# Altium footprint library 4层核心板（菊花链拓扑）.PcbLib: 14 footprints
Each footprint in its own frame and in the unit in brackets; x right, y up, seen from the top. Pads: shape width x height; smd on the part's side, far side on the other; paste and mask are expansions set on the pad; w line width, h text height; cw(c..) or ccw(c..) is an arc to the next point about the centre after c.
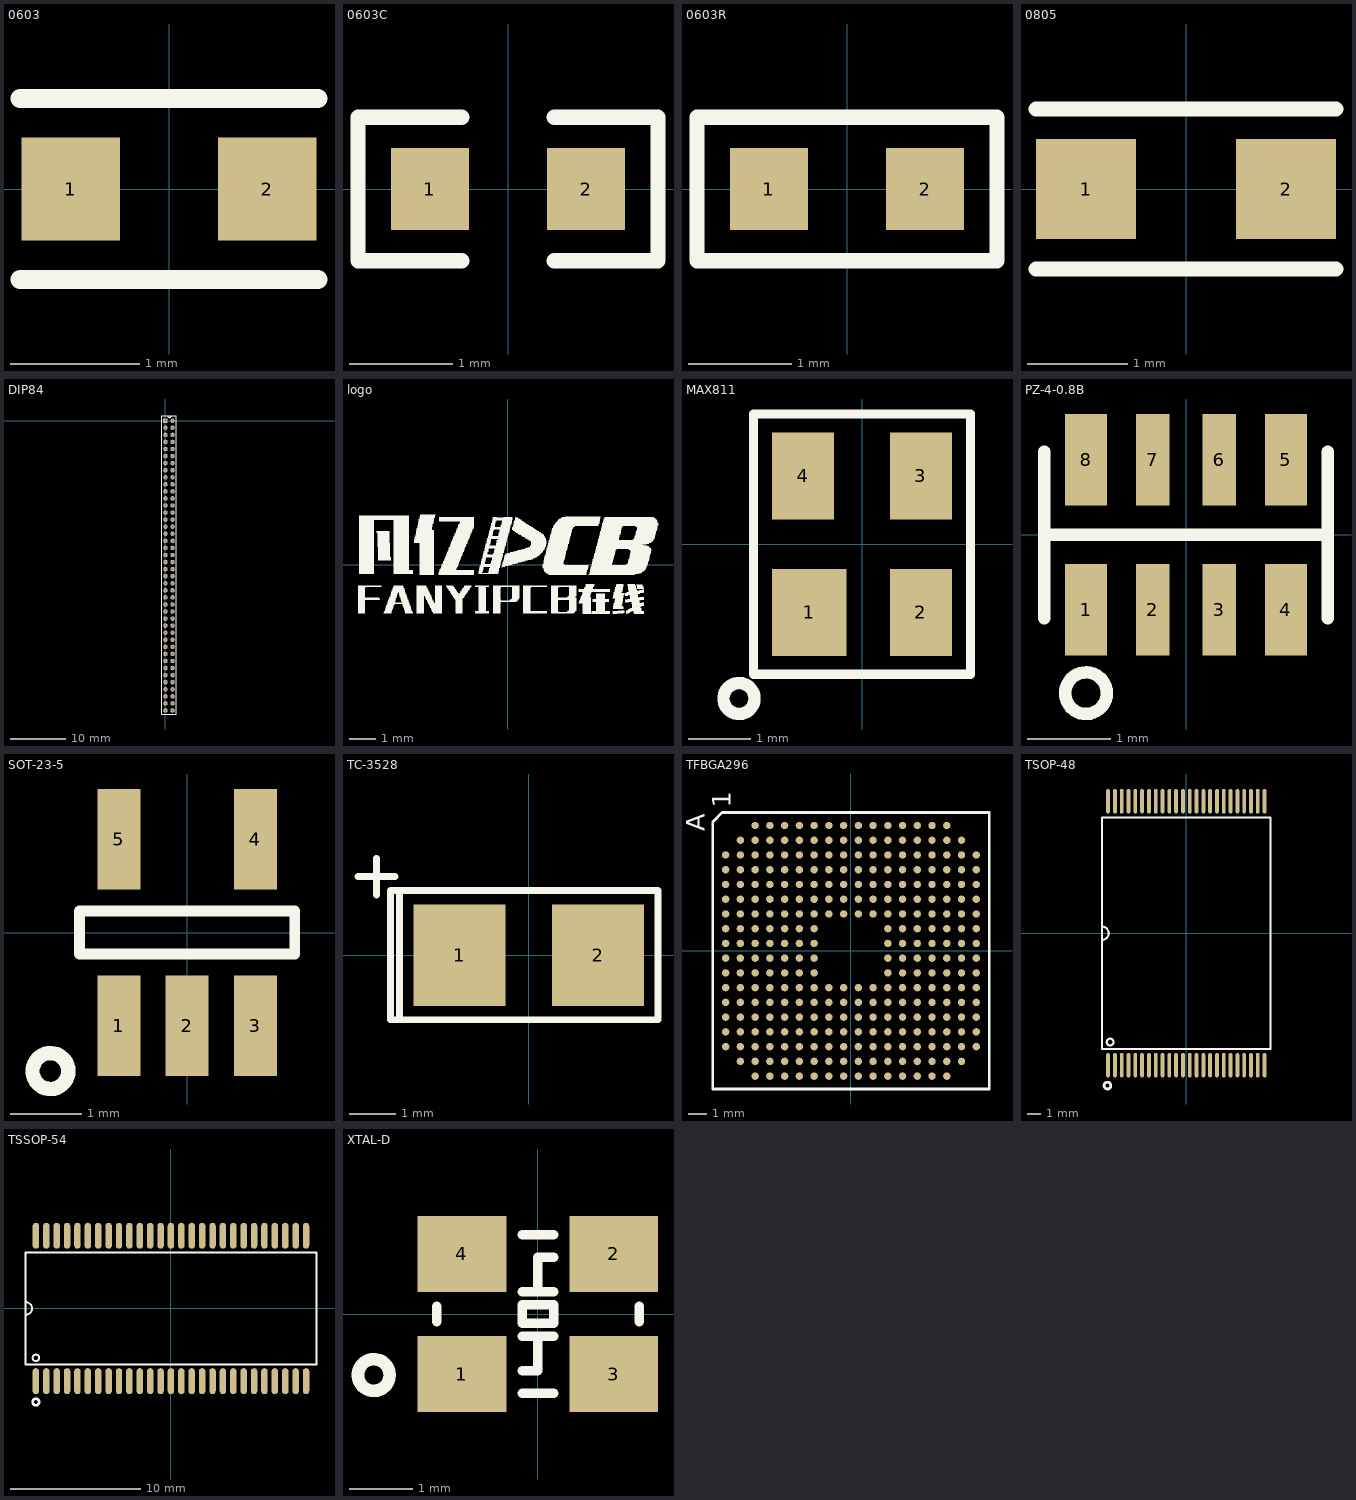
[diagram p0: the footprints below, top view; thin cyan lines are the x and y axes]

## 0603 [mm]
pads (2):
  rect 0.76x0.8 smd: 1(-0.76,0) 2(0.76,0)
Top Overlay:
  lines w0.15: -1.15,-0.7 1.15,-0.7 ; -1.15,0.7 1.15,0.7

## 0603C [mm]
pads (2):
  rect 0.76x0.8 smd: 1(-0.76,0) 2(0.76,0)
Top Overlay:
  lines w0.15: -0.45,-0.7 -1.46,-0.7 -1.46,0.7 -0.45,0.7 ; 0.45,-0.7 1.46,-0.7 1.46,0.7 0.45,0.7

## 0603R [mm]
pads (2):
  rect 0.76x0.8 smd: 1(-0.76,0) 2(0.76,0)
Top Overlay:
  lines w0.15: -1.46,-0.7 -1.46,0.7 1.46,0.7 1.46,-0.7 -1.46,-0.7

## 0805 [mm]
pads (2):
  rect 1x1 smd: 1(-1,0) 2(1,0)
Top Overlay:
  lines w0.15: -1.5,-0.8 1.5,-0.8 ; -1.5,0.8 1.5,0.8

## DIP84 [mm]
pads (84):
  rect 0.8x0.8 hole 0.55: 1(0,0)
  round 0.8 hole 0.55: 2(1.27,0) 3(0,-1.27) 4(1.27,-1.27) 5(0,-2.54) 6(1.27,-2.54) 7(0,-3.81) 8(1.27,-3.81) 9(0,-5.08) 10(1.27,-5.08) 11(0,-6.35) 12(1.27,-6.35) 13(0,-7.62) 14(1.27,-7.62) 15(0,-8.89) 16(1.27,-8.89) 17(0,-10.16) 18(1.27,-10.16) 19(0,-11.43) 20(1.27,-11.43) 21(0,-12.7) 22(1.27,-12.7) 23(0,-13.97) 24(1.27,-13.97) 25(0,-15.24) 26(1.27,-15.24) 27(0,-16.51) 28(1.27,-16.51) 29(0,-17.78) 30(1.27,-17.78) 31(0,-19.05) 32(1.27,-19.05) 33(0,-20.32) 34(1.27,-20.32) 35(0,-21.59) 36(1.27,-21.59) 37(0,-22.86) 38(1.27,-22.86) 39(0,-24.13) 40(1.27,-24.13) 41(0,-25.4) 42(1.27,-25.4) 43(0,-26.67) 44(1.27,-26.67) 45(0,-27.94) 46(1.27,-27.94) 47(0,-29.21) 48(1.27,-29.21) 49(0,-30.48) 50(1.27,-30.48) 51(0,-31.75) 52(1.27,-31.75) 53(0,-33.02) 54(1.27,-33.02) 55(0,-34.29) 56(1.27,-34.29) 57(0,-35.56) 58(1.27,-35.56) 59(0,-36.83) 60(1.27,-36.83) 61(0,-38.1) 62(1.27,-38.1) 63(0,-39.37) 64(1.27,-39.37) 65(0,-40.64) 66(1.27,-40.64) 67(0,-41.91) 68(1.27,-41.91) 69(0,-43.18) 70(1.27,-43.18) 71(0,-44.45) 72(1.27,-44.45) 73(0,-45.72) 74(1.27,-45.72) 75(0,-46.99) 76(1.27,-46.99) 77(0,-48.26) 78(1.27,-48.26) 79(0,-49.53) 80(1.27,-49.53) 81(0,-50.8) 82(1.27,-50.8) 83(0,-52.07) 84(1.27,-52.07)
Top Overlay:
  lines w0.15: 0.381,0.889 ccw(c0.699,0.889) 1.016,0.889 ; -0.635,-52.705 1.905,-52.705 1.905,0.889 -0.635,0.889 -0.635,-52.705

## logo [mm]
Top Overlay:
  drawing of 1471 lines, arcs and shapes, not listed

## MAX811 [mm]
pads (4):
  rect 1.2x1.4 smd: 1(-0.85,-1.1)
  rect 1x1.4 smd: 2(0.95,-1.1) 3(0.95,1.1) 4(-0.95,1.1)
Top Overlay:
  circle w0.2: c-1.985,-2.489 r0.25
  lines w0.15: -1.6,2.1 1.75,2.1 1.75,-2.1 -1.75,-2.1 -1.75,2.1 -1.5,2.1

## PZ-4-0.8B [mm]
pads (8):
  rect 0.5x1.1 smd: 1(-1.2,-0.9) 4(1.2,-0.9) 5(1.2,0.9) 8(-1.2,0.9)
  rect 0.4x1.1 smd: 2(-0.4,-0.9) 3(0.4,-0.9) 6(0.4,0.9) 7(-0.4,0.9)
Top Overlay:
  circle w0.15: c-1.2,-1.9 r0.25
  lines w0.15: -1.7,-1 -1.7,1 ; -1.7,0 1.7,0 ; 1.7,-1 1.7,1

## SOT-23-5 [mm]
pads (5):
  rect 0.6x1.4 smd: 1(-0.95,-1.3) 2(0,-1.3) 3(0.95,-1.3) 4(0.95,1.3) 5(-0.95,1.3)
Top Overlay:
  circle w0.2: c-1.905,-1.931 r0.25
  lines w0.15: -1.5,-0.3 -1.5,0.3 1.5,0.3 1.5,-0.3 -1.5,-0.3

## TC-3528 [mm]
pads (2):
  rect 2x2.2 smd: 1(-1.5,0) 2(1.5,0)
Top Overlay:
  lines w0.15: -3.7,1.7 -2.9,1.7 ; -3.3,1.3 -3.3,2.1 ; -2.8,-1.4 -3,-1.4 -3,1.4 -2.8,1.4 ; -2.8,-1.4 -2.8,1.4 ; -2.8,-1.4 2.8,-1.4 2.8,1.4 -2.8,1.4

## TFBGA296 [mm]
pads (296):
  round 0.4 smd: A3(-5.2,6.8) A4(-4.4,6.8) A5(-3.6,6.8) A6(-2.8,6.8) A7(-2,6.8) A8(-1.2,6.8) A9(-0.4,6.8) A10(0.4,6.8) A11(1.2,6.8) A12(2,6.8) A13(2.8,6.8) A14(3.6,6.8) A15(4.4,6.8) A16(5.2,6.8) B2(-6,6) B3(-5.2,6) B4(-4.4,6) B5(-3.6,6) B6(-2.8,6) B7(-2,6) B8(-1.2,6) B9(-0.4,6) B10(0.4,6) B11(1.2,6) B12(2,6) B13(2.8,6) B14(3.6,6) B15(4.4,6) B16(5.2,6) B17(6,6) C1(-6.8,5.2) C2(-6,5.2) C3(-5.2,5.2) C4(-4.4,5.2) C5(-3.6,5.2) C6(-2.8,5.2) C7(-2,5.2) C8(-1.2,5.2) C9(-0.4,5.2) C10(0.4,5.2) C11(1.2,5.2) C12(2,5.2) C13(2.8,5.2) C14(3.6,5.2) C15(4.4,5.2) C16(5.2,5.2) C17(6,5.2) C18(6.8,5.2) D1(-6.8,4.4) D2(-6,4.4) D3(-5.2,4.4) D4(-4.4,4.4) D5(-3.6,4.4) D6(-2.8,4.4) D7(-2,4.4) D8(-1.2,4.4) D9(-0.4,4.4) D10(0.4,4.4) D11(1.2,4.4) D12(2,4.4) D13(2.8,4.4) D14(3.6,4.4) D15(4.4,4.4) D16(5.2,4.4) D17(6,4.4) D18(6.8,4.4) E1(-6.8,3.6) E2(-6,3.6) E3(-5.2,3.6) E4(-4.4,3.6) E5(-3.6,3.6) E6(-2.8,3.6) E7(-2,3.6) E8(-1.2,3.6) E9(-0.4,3.6) E10(0.4,3.6) E11(1.2,3.6) E12(2,3.6) E13(2.8,3.6) E14(3.6,3.6) E15(4.4,3.6) E16(5.2,3.6) E17(6,3.6) E18(6.8,3.6) F1(-6.8,2.8) F2(-6,2.8) F3(-5.2,2.8) F4(-4.4,2.8) F5(-3.6,2.8) F6(-2.8,2.8) F7(-2,2.8) F8(-1.2,2.8) F9(-0.4,2.8) F10(0.4,2.8) F11(1.2,2.8) F12(2,2.8) F13(2.8,2.8) F14(3.6,2.8) F15(4.4,2.8) F16(5.2,2.8) F17(6,2.8) F18(6.8,2.8) G1(-6.8,2) G2(-6,2) G3(-5.2,2) G4(-4.4,2) G5(-3.6,2) G6(-2.8,2) G7(-2,2) G8(-1.2,2) G9(-0.4,2) G10(0.4,2) G11(1.2,2) G12(2,2) G13(2.8,2) G14(3.6,2) G15(4.4,2) G16(5.2,2) G17(6,2) G18(6.8,2) H1(-6.8,1.2) H2(-6,1.2) H3(-5.2,1.2) H4(-4.4,1.2) H5(-3.6,1.2) H6(-2.8,1.2) H7(-2,1.2) H12(2,1.2) H13(2.8,1.2) H14(3.6,1.2) H15(4.4,1.2) H16(5.2,1.2) H17(6,1.2) H18(6.8,1.2) J1(-6.8,0.4) J2(-6,0.4) J3(-5.2,0.4) J4(-4.4,0.4) J5(-3.6,0.4) J6(-2.8,0.4) J7(-2,0.4) J12(2,0.4) J13(2.8,0.4) J14(3.6,0.4) J15(4.4,0.4) J16(5.2,0.4) J17(6,0.4) J18(6.8,0.4) K1(-6.8,-0.4) K2(-6,-0.4) K3(-5.2,-0.4) K4(-4.4,-0.4) K5(-3.6,-0.4) K6(-2.8,-0.4) K7(-2,-0.4) K12(2,-0.4) K13(2.8,-0.4) K14(3.6,-0.4) K15(4.4,-0.4) K16(5.2,-0.4) K17(6,-0.4) K18(6.8,-0.4) L1(-6.8,-1.2) L2(-6,-1.2) L3(-5.2,-1.2) L4(-4.4,-1.2) L5(-3.6,-1.2) L6(-2.8,-1.2) L7(-2,-1.2) L12(2,-1.2) L13(2.8,-1.2) L14(3.6,-1.2) L15(4.4,-1.2) L16(5.2,-1.2) L17(6,-1.2) L18(6.8,-1.2) M1(-6.8,-2) M2(-6,-2) M3(-5.2,-2) M4(-4.4,-2) M5(-3.6,-2) M6(-2.8,-2) M7(-2,-2) M8(-1.2,-2) M9(-0.4,-2) M10(0.4,-2) M11(1.2,-2) M12(2,-2) M13(2.8,-2) M14(3.6,-2) M15(4.4,-2) M16(5.2,-2) M17(6,-2) M18(6.8,-2) N1(-6.8,-2.8) N2(-6,-2.8) N3(-5.2,-2.8) N4(-4.4,-2.8) N5(-3.6,-2.8) N6(-2.8,-2.8) N7(-2,-2.8) N8(-1.2,-2.8) N9(-0.4,-2.8) N10(0.4,-2.8) N11(1.2,-2.8) N12(2,-2.8) N13(2.8,-2.8) N14(3.6,-2.8) N15(4.4,-2.8) N16(5.2,-2.8) N17(6,-2.8) N18(6.8,-2.8) P1(-6.8,-3.6) P2(-6,-3.6) P3(-5.2,-3.6) P4(-4.4,-3.6) P5(-3.6,-3.6) P6(-2.8,-3.6) P7(-2,-3.6) P8(-1.2,-3.6) P9(-0.4,-3.6) P10(0.4,-3.6) P11(1.2,-3.6) P12(2,-3.6) P13(2.8,-3.6) P14(3.6,-3.6) P15(4.4,-3.6) P16(5.2,-3.6) P17(6,-3.6) P18(6.8,-3.6) R1(-6.8,-4.4) R2(-6,-4.4) R3(-5.2,-4.4) R4(-4.4,-4.4) R5(-3.6,-4.4) R6(-2.8,-4.4) R7(-2,-4.4) R8(-1.2,-4.4) R9(-0.4,-4.4) R10(0.4,-4.4) R11(1.2,-4.4) R12(2,-4.4) R13(2.8,-4.4) R14(3.6,-4.4) R15(4.4,-4.4) R16(5.2,-4.4) R17(6,-4.4) R18(6.8,-4.4) T1(-6.8,-5.2) T2(-6,-5.2) T3(-5.2,-5.2) T4(-4.4,-5.2) T5(-3.6,-5.2) T6(-2.8,-5.2) T7(-2,-5.2) T8(-1.2,-5.2) T9(-0.4,-5.2) T10(0.4,-5.2) T11(1.2,-5.2) T12(2,-5.2) T13(2.8,-5.2) T14(3.6,-5.2) T15(4.4,-5.2) T16(5.2,-5.2) T17(6,-5.2) T18(6.8,-5.2) U2(-6,-6) U3(-5.2,-6) U4(-4.4,-6) U5(-3.6,-6) U6(-2.8,-6) U7(-2,-6) U8(-1.2,-6) U9(-0.4,-6) U10(0.4,-6) U11(1.2,-6) U12(2,-6) U13(2.8,-6) U14(3.6,-6) U15(4.4,-6) U16(5.2,-6) U17(6,-6) V3(-5.2,-6.8) V4(-4.4,-6.8) V5(-3.6,-6.8) V6(-2.8,-6.8) V7(-2,-6.8) V8(-1.2,-6.8) V9(-0.4,-6.8) V10(0.4,-6.8) V11(1.2,-6.8) V12(2,-6.8) V13(2.8,-6.8) V14(3.6,-6.8) V15(4.4,-6.8) V16(5.2,-6.8)
Top Overlay:
  lines w0.15: -7.5,-7.5 -7.5,7 -7,7.5 7.5,7.5 7.5,-7.5 -7.5,-7.5
  text "1" at -6.534,7.764 h1.02
  text "A" at -7.931,6.494 h1.02

## TSOP-48 [mm]
pads (48):
  oval 0.28x1.8 smd: 1(-5.75,-9.7) 2(-5.25,-9.7) 3(-4.75,-9.7) 4(-4.25,-9.7) 5(-3.75,-9.7) 6(-3.25,-9.7) 7(-2.75,-9.7) 8(-2.25,-9.7) 9(-1.75,-9.7) 10(-1.25,-9.7) 11(-0.75,-9.7) 12(-0.25,-9.7) 13(0.25,-9.7) 14(0.75,-9.7) 15(1.25,-9.7) 16(1.75,-9.7) 17(2.25,-9.7) 18(2.75,-9.7) 19(3.25,-9.7) 20(3.75,-9.7) 21(4.25,-9.7) 22(4.75,-9.7) 23(5.25,-9.7) 24(5.75,-9.7) 25(5.75,9.7) 26(5.25,9.7) 27(4.75,9.7) 28(4.25,9.7) 29(3.75,9.7) 30(3.25,9.7) 31(2.75,9.7) 32(2.25,9.7) 33(1.75,9.7) 34(1.25,9.7) 35(0.75,9.7) 36(0.25,9.7) 37(-0.25,9.7) 38(-0.75,9.7) 39(-1.25,9.7) 40(-1.75,9.7) 41(-2.25,9.7) 42(-2.75,9.7) 43(-3.25,9.7) 44(-3.75,9.7) 45(-4.25,9.7) 46(-4.75,9.7) 47(-5.25,9.7) 48(-5.75,9.7)
Top Overlay:
  circle w0.15: c-5.6,-8 r0.25
  circle w0.2: c-5.8,-11.2 r0.25
  lines w0.15: -6.2,-0.5 ccw(c-6.2,0) -6.2,0.5 ; -6.2,-8.5 -6.2,8.5 6.2,8.5 6.2,-8.5 -6.2,-8.5

## TSSOP-54 [mm]
pads (54):
  oval 0.5x2 smd: 1(-10.4,-5.6) 2(-9.6,-5.6) 3(-8.8,-5.6) 4(-8,-5.6) 5(-7.2,-5.6) 6(-6.4,-5.6) 7(-5.6,-5.6) 8(-4.8,-5.6) 9(-4,-5.6) 10(-3.2,-5.6) 11(-2.4,-5.6) 12(-1.6,-5.6) 13(-0.8,-5.6) 14(0,-5.6) 15(0.8,-5.6) 16(1.6,-5.6) 17(2.4,-5.6) 18(3.2,-5.6) 19(4,-5.6) 20(4.8,-5.6) 21(5.6,-5.6) 22(6.4,-5.6) 23(7.2,-5.6) 24(8,-5.6) 25(8.8,-5.6) 26(9.6,-5.6) 27(10.4,-5.6) 28(10.4,5.6) 29(9.6,5.6) 30(8.8,5.6) 31(8,5.6) 32(7.2,5.6) 33(6.4,5.6) 34(5.6,5.6) 35(4.8,5.6) 36(4,5.6) 37(3.2,5.6) 38(2.4,5.6) 39(1.6,5.6) 40(0.8,5.6) 41(0,5.6) 42(-0.8,5.6) 43(-1.6,5.6) 44(-2.4,5.6) 45(-3.2,5.6) 46(-4,5.6) 47(-4.8,5.6) 48(-5.6,5.6) 49(-6.4,5.6) 50(-7.2,5.6) 51(-8,5.6) 52(-8.8,5.6) 53(-9.6,5.6) 54(-10.4,5.6)
Top Overlay:
  circle w0.2: c-10.4,-7.2 r0.25
  circle w0.15: c-10.4,-3.8 r0.25
  lines w0.15: -11.2,-0.5 ccw(c-11.2,0) -11.2,0.5 ; -11.2,-4.3 11.2,-4.3 11.2,4.3 -11.2,4.3 -11.2,-4.3

## XTAL-D [mm]
pads (4):
  rect 1.4x1.2 smd: 1(-1.2,-0.95) 2(1.2,0.95) 3(1.2,-0.95) 4(-1.2,0.95)
Top Overlay:
  circle w0.2: c-2.595,-0.965 r0.25
  lines w0.15: -1.6,-0.12 -1.6,0.12 ; -0.25,-1.25 0.25,-1.25 ; -0.25,-0.9 0,-0.9 0,-0.35 ; -0.25,-0.35 0.25,-0.35 ; -0.25,0.35 0.25,0.35 ; -0.25,1.25 0.25,1.25 ; 0,0.35 0,0.9 0.25,0.9 ; 1.6,-0.12 1.6,0.12 ; -0.25,-0.15 -0.25,0.15 0.25,0.15 0.25,-0.15 -0.25,-0.15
